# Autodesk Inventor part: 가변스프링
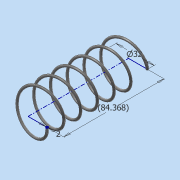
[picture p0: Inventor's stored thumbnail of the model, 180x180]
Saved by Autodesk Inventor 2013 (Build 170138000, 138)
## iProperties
Created: 2016-11
Part Number: 가변스프링
Material: 강철, 탄소
Document SubType Name: Modeling
Designer: dgall
Density: 7.87 g/cm^3
Mass: 14.8346 g
Surface Area: 38.0281 cm^2
Volume: 1.88496 cm^3
Author: dgall
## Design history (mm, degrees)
sketch "스케치1"
  geometry: L1 (16, 0)-(0, 0); L2 (0, 0)-(0, 84.368); L3 (0, 84.368)-(16, 84.368); C1 r 1 at (16, 0)
  constraints: 6 end point, 1 centre point, 1 coincident, 1 horizontal, 1 parallel, 1 perpendicular, 1 vertical alignment
  dimensions: "d0" = 2 diameter of C1; "d1" = 32 diameter of L3.end L2; "d2" = 84.36759 distance from line of L3 L1.start (derived)
feature "코일1" sketch "스케치1" pitch "d3" = 10; turns "d5" = 6; dims "d4" = 84.36759 (= d2), "d6" = 0, angle "d7" = 90 deg, angle "d8" = 90 deg, "d9" = 0, "d10" = 0
node "작업 평면1"
feature "분할1"
feature "분할2"
node "솔리드1"
